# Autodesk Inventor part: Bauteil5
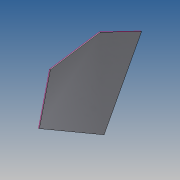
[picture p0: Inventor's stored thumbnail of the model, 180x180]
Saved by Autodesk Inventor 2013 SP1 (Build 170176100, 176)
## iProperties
Company: Kirow Ardelt GmbH
Created: 2013-01
Part Number: Bauteil5
Material: Stahl
Document SubType Name: Modellieren
Designer: Winkelmann
Density: 7.85 g/cm^3
Mass: 23816.8 g
Surface Area: 7777.97 cm^2
Volume: 3033.99 cm^3
Author: Winkelmann
Revision Number: A
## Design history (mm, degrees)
derived "Bauteil4.ipt"
  sketch "Skizze1"
    geometry: L1 (-318.13, 206.345)-(86.584, 266.588) reference; L2 (86.584, 266.588)-(420.194, 105.525) reference; L3 (420.194, 105.525)-(116.643, -467.157) reference; L4 (116.643, -467.157)-(-406.665, -162.026) reference; L5 (-406.665, -162.026)-(-318.13, 206.345) reference; 1 further point
tag "Bezeichnung1"
feature "Volumenkörper1::Bauteil4.ipt"
node "Volumenkörper1"
node "Volumenkörper2"
other parameters: "Stärke" = 8 (derived), "KFaktor" = 4.4, "Biegeradius" = 8 (= Stärke), "BreiteBiegungsfreistellung" = 8 (= Stärke), "TiefeBiegungsfreistellung" = 4 (= 0.5 x Stärke), "GrößeEckenfreistellung" = 32 (= 4 x Stärke), "AbstandVerbindung" = 0.01, "MinimalRest" = 16 (= 2 x Stärke), "Übergangsradius" = 8 (= Biegeradius), "JacobiRadiusGröße" = 8 (= Biegeradius), "Abstandsgröße" = 8 (= Stärke), "Stärke_1" = 8, "Biegeradius_1" = 8, "BreiteBiegungsfreistellung_1" = 8, "TiefeBiegungsfreistellung_1" = 4, "GrößeEckenfreistellung_1" = 32, "MinimalRest_1" = 16, "Übergangsradius_1" = 8, "JacobiRadiusGröße_1" = 8, "Abstandsgröße_1" = 8, "d0_1" = 8
